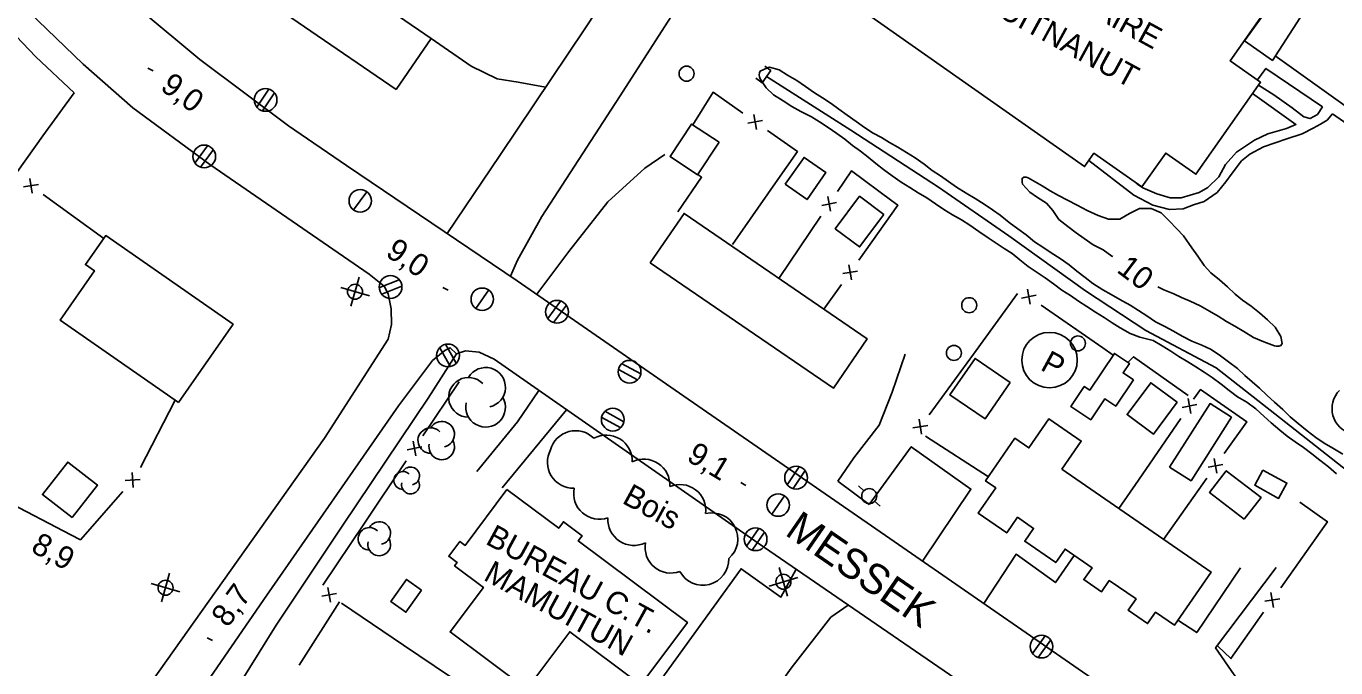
# Model space of a CAD drawing. Extents: x 219136 to 222520, y 5421589 to 5424530.
# Drawn here: x 221189.4 to 221364.2, y 5423246.8 to 5423332.5 of the extents above; entities that cross this region are included whole.
import ezdxf

# ---------------------------------------------------------------- set-up
doc = ezdxf.new("R2010")
doc.units = 0
for name, color, linetype in [('Level 1', 7, 'Continuous'), ('Level 19', 7, 'Continuous'), ('Level 2', 7, 'Continuous'), ('Level 21', 7, 'Continuous'), ('Level 22', 7, 'Continuous'), ('Level 26', 7, 'Continuous'), ('Level 3', 7, 'Continuous'), ('Level 31', 7, 'Continuous'), ('Level 36', 7, 'Continuous'), ('Level 37', 7, 'Continuous'), ('Level 38', 7, 'Continuous'), ('Level 4', 7, 'Continuous'), ('Level 44', 7, 'Continuous'), ('Level 52', 7, 'Continuous')]:
    doc.layers.add(name, color=color, linetype=linetype)

msp = doc.modelspace()

# ---------------------------------------------------------------- linework, layer by layer
at = {"layer": 'Level 1'}
for points in [[(221334.39, 5423301.7), (221334.28, 5423301.77), (221333.12, 5423302.6), (221331.78, 5423303.29), (221330.57, 5423304.11), (221329.51, 5423304.88), (221328.39, 5423305.71), (221327.21, 5423306.67), (221326.39, 5423307.87), (221325.54, 5423308.83), (221324.37, 5423309.6), (221323.34, 5423310.31), (221322.37, 5423311.37), (221322.31, 5423311.62), (221322.3, 5423312.14), (221322.54, 5423312.31), (221322.83, 5423312.29), (221323.11, 5423312.21), (221324.96, 5423311.14), (221326.03, 5423310.48), (221327.16, 5423309.85), (221328.35, 5423309.24), (221329.64, 5423308.56), (221330.99, 5423307.85), (221332.43, 5423307.21), (221333.85, 5423306.68), (221335.36, 5423306.71), (221336.64, 5423307.46)], [(221336.64, 5423307.46), (221337.98, 5423308.12), (221339.54, 5423308.11), (221340.84, 5423307.53), (221341.92, 5423306.49), (221342.96, 5423305.43), (221343.85, 5423304.46), (221344.97, 5423302.88), (221345.73, 5423301.75), (221346.58, 5423300.53), (221347.5, 5423299.54), (221348.65, 5423298.59), (221349.69, 5423297.65), (221350.72, 5423296.7), (221351.7, 5423295.89), (221352.87, 5423295.09), (221353.99, 5423294.18), (221355.03, 5423293.26), (221356.08, 5423292.28), (221356.84, 5423291.06), (221357, 5423290.1), (221356.84, 5423289.85), (221356.56, 5423289.75), (221356.24, 5423289.75), (221355.96, 5423289.8), (221354.54, 5423290.31), (221353.18, 5423290.93), (221351.87, 5423291.71), (221350.67, 5423292.41), (221349.59, 5423293.05), (221348.48, 5423293.75), (221347.32, 5423294.43), (221346.08, 5423295.15), (221344.72, 5423295.75), (221343.57, 5423296.23), (221342.53, 5423296.74)], [(221342.53, 5423296.74), (221341.2, 5423297.25), (221340.4, 5423297.67)]]:
    msp.add_lwpolyline(points, dxfattribs=at)
at = {"layer": 'Level 19'}
for points in [[(221243.46, 5423330.83), (221248.79, 5423327.14), (221252.25, 5423325.43), (221255.05, 5423325), (221258.72, 5423324.32), (221258.72, 5423324.32)], [(221188.24, 5423313.07), (221191.65, 5423317.82), (221195.82, 5423323.56)], [(221257.56, 5423296.68), (221261.82, 5423302.4), (221267.04, 5423309), (221271.97, 5423313.5), (221274.63, 5423315.35)], [(221297.7, 5423271.73), (221299.84, 5423274.83), (221303.25, 5423279.2), (221304.96, 5423283.62), (221306.72, 5423288.7)], [(221249.54, 5423273.01), (221254.97, 5423279.64), (221257.8, 5423283.85)], [(221261.53, 5423281.26), (221252.91, 5423270.85)], [(221301.91, 5423268.64), (221307.52, 5423276.33), (221315.47, 5423270.68), (221308.99, 5423261.08)], [(221317.2, 5423255.4), (221321.49, 5423261.98), (221326.75, 5423258.19), (221329.25, 5423261.83)], [(221351.46, 5423260.17), (221345.61, 5423251.52), (221343.1, 5423253.2)], [(221356.18, 5423260.23), (221348.12, 5423249.48), (221350.59, 5423245.9), (221354.2, 5423241.31), (221357.6, 5423238.87), (221360.7, 5423236.89), (221366.13, 5423232.73), (221367.98, 5423235.4)]]:
    msp.add_lwpolyline(points, dxfattribs=at)
at = {"layer": 'Level 2'}
for points in [[(221302.45, 5423318.2), (221301.29, 5423318.95), (221300.14, 5423319.75), (221298.96, 5423320.58), (221297.85, 5423321.39), (221296.81, 5423322.13), (221295.66, 5423322.88), (221294.6, 5423323.54), (221293.38, 5423324.42), (221292.23, 5423325.22), (221291.02, 5423325.94), (221289.89, 5423326.65), (221288.6, 5423326.98), (221288.32, 5423326.92), (221287.36, 5423326.47), (221287.26, 5423326.22), (221287.23, 5423325.96), (221287.26, 5423325.69), (221287.34, 5423325.44), (221288.13, 5423324.23), (221289.14, 5423323.28), (221290.44, 5423322.48), (221291.59, 5423321.76), (221292.79, 5423321.09), (221294.19, 5423320.38), (221295.27, 5423319.71), (221296.42, 5423318.95), (221297.57, 5423318.14), (221298.64, 5423317.36), (221299.68, 5423316.55), (221300.73, 5423315.77), (221301.76, 5423314.97), (221302.78, 5423314.13), (221303.8, 5423313.31), (221304.95, 5423312.47), (221306.18, 5423311.63), (221307.3, 5423310.91), (221308.45, 5423310.22), (221309.61, 5423309.53), (221310.76, 5423308.74), (221311.88, 5423307.98), (221313.03, 5423307.3), (221314.22, 5423306.61), (221315.32, 5423305.92), (221316.55, 5423305.06), (221317.77, 5423304.2), (221318.84, 5423303.5), (221319.93, 5423302.78), (221320.99, 5423302.1), (221321.98, 5423301.26), (221323.1, 5423300.4), (221324.31, 5423299.57), (221325.38, 5423298.85), (221326.48, 5423298.09), (221327.6, 5423297.24), (221328.75, 5423296.5), (221329.83, 5423295.78), (221330.94, 5423295.03), (221332.1, 5423294.31), (221333.23, 5423293.59), (221334.31, 5423292.88), (221335.38, 5423292.18), (221336.71, 5423291.46), (221338.02, 5423290.94), (221338.54, 5423290.83)], [(221365.11, 5423275.36), (221363.76, 5423276.13), (221362.6, 5423276.79), (221361.5, 5423277.56), (221360.35, 5423278.47), (221359.13, 5423279.45), (221358.09, 5423280.34), (221357.08, 5423281.28), (221356, 5423282.28), (221354.94, 5423283.21), (221353.96, 5423284.13), (221352.99, 5423284.98), (221352, 5423285.84), (221351.04, 5423286.78), (221349.82, 5423287.64), (221348.61, 5423288.59), (221347.46, 5423289.34), (221346.29, 5423289.87), (221344.97, 5423290.42), (221343.64, 5423291.1), (221342.52, 5423291.75), (221341.34, 5423292.39), (221340.11, 5423293.01), (221338.94, 5423293.79), (221337.82, 5423294.52), (221336.7, 5423295.24), (221335.35, 5423295.99), (221334.18, 5423296.65), (221333.07, 5423297.28), (221331.75, 5423298.12), (221330.7, 5423298.92), (221329.61, 5423299.77), (221328.56, 5423300.6), (221327.36, 5423301.43), (221326.2, 5423302.19), (221325.06, 5423302.95), (221323.97, 5423303.69), (221322.86, 5423304.59), (221321.71, 5423305.42), (221320.57, 5423306.26), (221319.39, 5423307.23), (221318.37, 5423307.96), (221317.24, 5423308.7), (221316.06, 5423309.47), (221314.82, 5423310.18), (221313.54, 5423310.97), (221312.49, 5423311.72), (221311.4, 5423312.47), (221310.32, 5423313.2), (221309.24, 5423314.03), (221308.04, 5423314.88), (221306.88, 5423315.6), (221305.74, 5423316.29), (221304.63, 5423316.94), (221303.56, 5423317.59), (221302.45, 5423318.2)], [(221338.54, 5423290.83), (221339.79, 5423290.49), (221340.99, 5423289.81), (221342.14, 5423289.09), (221343.21, 5423288.38), (221344.4, 5423287.65), (221345.5, 5423286.98), (221346.58, 5423286.29), (221347.68, 5423285.56), (221348.85, 5423284.7), (221349.93, 5423283.83), (221351.06, 5423283.01), (221352.3, 5423282.28), (221353.49, 5423281.38), (221354.59, 5423280.35), (221355.54, 5423279.51), (221356.71, 5423278.53), (221357.69, 5423277.74), (221358.72, 5423276.99), (221359.83, 5423276.22), (221360.95, 5423275.38), (221362.03, 5423274.55), (221363.17, 5423273.64), (221364.25, 5423272.71)]]:
    msp.add_lwpolyline(points, dxfattribs=at)
at = {"layer": 'Level 21'}
for points in [[(221166.57, 5423470.95), (221167.05, 5423466.85), (221167.99, 5423465.31), (221169.33, 5423463.67), (221170.84, 5423462.49), (221172.03, 5423461.9), (221173.9, 5423444.53), (221176.37, 5423413.28), (221177.95, 5423395.01), (221178.79, 5423388.11), (221180.59, 5423381.09), (221181.46, 5423378.86), (221186.24, 5423366.21), (221184.71, 5423363.79), (221184.17, 5423361.06), (221184.79, 5423358.59), (221185.99, 5423356.51), (221188.89, 5423351.93), (221194.15, 5423345.11), (221198.89, 5423340.19), (221204.64, 5423334.62), (221212.6, 5423328.01), (221224.42, 5423319.14), (221232.14, 5423313.85)], [(221245.61, 5423304.77), (221252.61, 5423315.21), (221264.03, 5423332.23), (221275.63, 5423349.82), (221288.07, 5423368.7), (221299.26, 5423385.38), (221309.36, 5423398.65), (221319.83, 5423409.55), (221328.62, 5423417.49)], [(221335.26, 5423410.11), (221329.06, 5423403.64), (221327.51, 5423400.23), (221322.49, 5423394.42), (221319.72, 5423395.45), (221317.02, 5423394.19), (221314.06, 5423390.87), (221310.44, 5423385.78), (221301.43, 5423371.69), (221293.71, 5423361.29), (221281.55, 5423343.25), (221268.57, 5423323.02), (221258.2, 5423307.05), (221254.98, 5423301.25), (221254.03, 5423299.11)], [(221195.82, 5423323.56), (221190.7, 5423328.36), (221187.21, 5423332.07), (221180.66, 5423340.32), (221175.98, 5423347.03), (221172.93, 5423353.25), (221170.5, 5423359.06), (221169.55, 5423362.68)], [(221187.7, 5423218.3), (221205.22, 5423243.64), (221229.21, 5423277.47), (221237.71, 5423290.69), (221238.14, 5423292.63), (221238.13, 5423294.72), (221237.7, 5423296.72), (221237.17, 5423297.75), (221235.16, 5423299.35), (221213.94, 5423313.98), (221203.63, 5423321.56), (221197.02, 5423327.41), (221187.38, 5423336.74)], [(221232.14, 5423313.85), (221254.94, 5423298.49), (221276.61, 5423283.49), (221305.25, 5423263.67), (221335.68, 5423242.61), (221372.49, 5423217.23)], [(221160.77, 5423162.07), (221179.61, 5423192.27), (221195.24, 5423218.18), (221207.37, 5423235.95), (221221.52, 5423256.52), (221239.08, 5423281.8), (221243.65, 5423287.85), (221245.26, 5423289.18), (221245.97, 5423289.53), (221246.85, 5423288.72), (221248.05, 5423289.14), (221249.86, 5423288.94), (221251.84, 5423288), (221287.09, 5423263.46), (221326.07, 5423236.66), (221356.72, 5423215.77), (221381.01, 5423198.93), (221382.03, 5423197.83), (221382.77, 5423196), (221383.04, 5423193.74), (221382.84, 5423191.9), (221382.48, 5423188.97), (221374.16, 5423163.4), (221366.95, 5423136.57)], [(221246.85, 5423288.72), (221243.05, 5423282.81), (221231.66, 5423265.88), (221222.75, 5423252.5), (221214.52, 5423239.23), (221207.59, 5423226.74), (221198.22, 5423212.24), (221189.81, 5423198.56), (221182.61, 5423188.58), (221175.53, 5423179.21), (221170.03, 5423170.75), (221165.83, 5423165.23), (221163.7, 5423164.25), (221162.66, 5423162.72), (221162.1, 5423161.37)], [(221301.91, 5423268.64), (221297.7, 5423271.73)]]:
    msp.add_lwpolyline(points, dxfattribs=at)
at = {"layer": 'Level 22'}
for points in [[(221356.08, 5423328.5), (221375.51, 5423314.62)], [(221362.37, 5423321.69), (221354.84, 5423326.81), (221353.7, 5423325.28)], [(221353.06, 5423323.46), (221358.84, 5423319.35), (221357.57, 5423318.81), (221355.07, 5423318.07), (221353.32, 5423317.24), (221350.89, 5423315.65), (221349.44, 5423314), (221348.56, 5423312.35), (221347.1, 5423310.92), (221345.91, 5423310.27), (221343.54, 5423309.55), (221342.04, 5423309.57), (221340.26, 5423310.1), (221338.39, 5423310.88), (221337.62, 5423311.41)], [(221362.37, 5423321.69), (221361.7, 5423320.68), (221360.76, 5423320.13), (221359.9, 5423320.38), (221358.34, 5423321.58), (221355.9, 5423323.3), (221353.84, 5423324.58)], [(221331.19, 5423314.51), (221337.21, 5423309.9), (221339.73, 5423308.58), (221341.96, 5423308.01), (221343.78, 5423308.1), (221345.16, 5423308.6), (221346.58, 5423309.06), (221348.31, 5423310.28), (221349.5, 5423311.69), (221350.33, 5423312.85), (221351.56, 5423314.48), (221352.69, 5423315.38), (221354.53, 5423316.35), (221357.61, 5423317.44), (221359.68, 5423318.09), (221361.13, 5423318.86), (221362.1, 5423319.38), (221363, 5423319.91), (221363.72, 5423320.76)], [(221372.85, 5423314.4), (221363.72, 5423320.76)]]:
    msp.add_lwpolyline(points, dxfattribs=at)
at = {"layer": 'Level 26'}
for p, q in [((221288.79, 5423326.54), (221287.98, 5423327.13)), ((221287.6, 5423324.91), (221286.79, 5423325.5)), ((221288.79, 5423326.54), (221287.6, 5423324.91))]:
    msp.add_line(p, q, dxfattribs=at)
at = {"layer": 'Level 3'}
for p, q in [((221205.65, 5423326.86), (221206.35, 5423326.48)), ((221245.01, 5423297.59), (221245.71, 5423297.21)), ((221284.76, 5423271.54), (221285.46, 5423271.16)), ((221213.56, 5423250.83), (221214.27, 5423250.45))]:
    msp.add_line(p, q, dxfattribs=at)
at = {"layer": 'Level 31'}
for points in [[(221238.79, 5423324.01), (221214.32, 5423340.76), (221218.99, 5423347.58), (221243.46, 5423330.83)], [(221281.87, 5423316.96), (221279.01, 5423312.63), (221275.34, 5423315.06), (221278.19, 5423319.39)], [(221290.7, 5423311.36), (221293.21, 5423314.95), (221296.12, 5423312.91), (221293.61, 5423309.32)], [(221303.87, 5423307.31), (221300.61, 5423302.99), (221297.36, 5423305.43), (221300.62, 5423309.76)], [(221272.68, 5423300.88), (221297.12, 5423284.13), (221301.63, 5423290.71), (221277.19, 5423307.46)], [(221209.73, 5423282.22), (221193.93, 5423293.23), (221198.52, 5423299.81), (221197.33, 5423300.64), (221200.04, 5423304.51), (221217.02, 5423292.68)], [(221337.15, 5423285.26), (221334.79, 5423281.76), (221333.35, 5423282.73), (221331.46, 5423279.93), (221328.8, 5423281.72), (221330.6, 5423284.39), (221331.33, 5423283.9), (221334.62, 5423288.79), (221336.63, 5423287.44), (221335.78, 5423286.18)], [(221320.7, 5423284.92), (221317.36, 5423280.04), (221312.68, 5423283.24), (221316.03, 5423288.12)], [(221342.98, 5423282.27), (221339.84, 5423278.02), (221336.32, 5423280.62), (221339.47, 5423284.87)], [(221341.99, 5423273.62), (221347.38, 5423282.08), (221350.24, 5423280.26), (221344.85, 5423271.8)], [(221327.61, 5423273.33), (221347.52, 5423259.6), (221342.62, 5423252.51), (221340.09, 5423254.25), (221339.04, 5423252.73), (221336.46, 5423254.51), (221337.5, 5423256.02), (221333.94, 5423258.47), (221332.89, 5423256.95), (221330.52, 5423258.59), (221331.63, 5423260.19), (221328.03, 5423262.67), (221326.79, 5423260.87), (221322.65, 5423263.72), (221323.84, 5423265.43), (221321.7, 5423266.91), (221320.25, 5423264.82), (221316.45, 5423267.45), (221318.78, 5423270.83), (221317.42, 5423271.77), (221321.34, 5423277.46), (221323.2, 5423276.18), (221325.88, 5423280.06), (221330.19, 5423277.09)], [(221195.56, 5423266.87), (221198.93, 5423271.22), (221194.96, 5423274.29), (221191.59, 5423269.94)], [(221351.94, 5423266.65), (221347.3, 5423270.23), (221349.54, 5423273.13), (221354.18, 5423269.55)], [(221354.44, 5423273.21), (221357.63, 5423271.47), (221356.52, 5423269.44), (221353.34, 5423271.18)], [(221253.57, 5423270.61), (221260.47, 5423265.46), (221261.11, 5423266.32), (221263.6, 5423264.46), (221263.08, 5423263.77), (221277.64, 5423252.89), (221271.42, 5423244.56), (221261.94, 5423251.64), (221256.22, 5423243.97), (221245.98, 5423251.61), (221250.42, 5423257.56), (221246.57, 5423260.44), (221246.9, 5423260.89), (221245.8, 5423261.71), (221247.28, 5423263.69), (221248, 5423263.15)], [(221242.18, 5423257.17), (221240.09, 5423254.23), (221238.06, 5423255.68), (221240.15, 5423258.62)]]:
    msp.add_lwpolyline(points, close=True, dxfattribs=at)
msp.add_lwpolyline([(221354.39, 5423333.98), (221350.07, 5423327.82), (221354.12, 5423324.98), (221345.49, 5423312.69), (221341.46, 5423315.52), (221338.29, 5423311.01), (221331.88, 5423315.5), (221330.64, 5423313.73), (221301.34, 5423334.29)], dxfattribs=at)
at = {"layer": 'Level 36'}
for p, q in [((221221.79, 5423324.07), (221220.18, 5423321.66)), ((221220.95, 5423321.17), (221222.56, 5423323.58)), ((221213.63, 5423316.51), (221211.93, 5423314.16)), ((221212.69, 5423313.63), (221214.39, 5423315.98)), ((221234.88, 5423310.36), (221233.1, 5423307.94)), ((221233.84, 5423298.94), (221232.74, 5423295.11)), ((221231.38, 5423297.58), (221235.21, 5423296.48)), ((221239.18, 5423298.62), (221236.49, 5423297.52)), ((221236.86, 5423296.68), (221239.55, 5423297.78)), ((221251.13, 5423297.25), (221249.41, 5423294.79)), ((221260.73, 5423295.77), (221259.01, 5423293.44)), ((221259.77, 5423292.91), (221261.49, 5423295.24)), ((221246.81, 5423287.48), (221245.38, 5423290)), ((221244.59, 5423289.52), (221246.02, 5423287)), ((221268.45, 5423286.64), (221270.99, 5423285.25)), ((221271.41, 5423286.06), (221268.87, 5423287.45)), ((221266.21, 5423280.25), (221268.75, 5423278.86)), ((221269.17, 5423279.67), (221266.63, 5423281.06)), ((221292.57, 5423273.66), (221290.97, 5423271.23)), ((221291.75, 5423270.74), (221293.35, 5423273.17)), ((221300.45, 5423271.12), (221301.17, 5423270.43)), ((221288.9, 5423267.31), (221290.6, 5423269.77)), ((221303.36, 5423268.38), (221302.62, 5423269.05)), ((221287.17, 5423265.42), (221285.52, 5423263.04)), ((221286.29, 5423262.54), (221287.94, 5423264.92)), ((221208.56, 5423259.44), (221207.46, 5423255.61)), ((221288.54, 5423257.74), (221292.37, 5423258.87)), ((221291.02, 5423256.39), (221289.89, 5423260.22)), ((221206.1, 5423258.08), (221209.93, 5423256.98)), ((221325.37, 5423251.1), (221323.67, 5423248.75)), ((221324.43, 5423248.22), (221326.13, 5423250.57))]:
    msp.add_line(p, q, dxfattribs=at)
for centre, radius in [((221277.53, 5423326.12), 1), ((221221.36, 5423322.62), 1.52), ((221213.17, 5423315.07), 1.52), ((221233.99, 5423309.14), 1.5), ((221238.03, 5423297.65), 1.52), ((221233.29, 5423297.02), 1), ((221250.27, 5423296.01), 1.5), ((221260.24, 5423294.34), 1.52), ((221315.24, 5423295.22), 1), ((221245.7, 5423288.51), 1.52), ((221329.75, 5423290.12), 1), ((221313.2, 5423288.85), 1), ((221269.93, 5423286.34), 1.52), ((221267.69, 5423279.95), 1.52), ((221292.15, 5423272.2), 1.52), ((221301.9, 5423269.74), 1), ((221289.75, 5423268.55), 1.5), ((221286.74, 5423263.98), 1.52), ((221208.01, 5423257.52), 1), ((221290.46, 5423258.31), 1), ((221324.89, 5423249.66), 1.52)]:
    msp.add_circle(centre, radius, dxfattribs=at)
at = {"layer": 'Level 37'}
for p, q in [((221285.71, 5423319.51), (221287.68, 5423319.85)), ((221286.87, 5423318.69), (221286.52, 5423320.67)), ((221191.05, 5423311.32), (221189.07, 5423311.01)), ((221189.9, 5423312.15), (221190.21, 5423310.17)), ((221296.75, 5423307.75), (221296.37, 5423309.72)), ((221297.54, 5423308.93), (221295.58, 5423308.54)), ((221299.19, 5423300.59), (221299.53, 5423298.62)), ((221298.37, 5423299.44), (221300.35, 5423299.77)), ((221323.38, 5423295.37), (221323.03, 5423297.34)), ((221322.22, 5423296.18), (221324.19, 5423296.54)), ((221343.65, 5423281.58), (221345.61, 5423281.95)), ((221344.45, 5423282.75), (221344.81, 5423280.78)), ((221308.89, 5423278.01), (221308.57, 5423279.99)), ((221309.72, 5423279.15), (221307.74, 5423278.84)), ((221242.21, 5423276.3), (221240.25, 5423275.92)), ((221241.42, 5423275.13), (221241.04, 5423277.09)), ((221348.28, 5423272.79), (221347.94, 5423274.76)), ((221203.68, 5423270.88), (221203.55, 5423272.87)), ((221349.1, 5423273.94), (221347.13, 5423273.6)), ((221204.61, 5423271.94), (221202.62, 5423271.81)), ((221230.82, 5423256.75), (221228.86, 5423256.37)), ((221229.65, 5423257.54), (221230.03, 5423255.58)), ((221355.85, 5423254.88), (221355.51, 5423256.86)), ((221356.67, 5423256.04), (221354.69, 5423255.7))]:
    msp.add_line(p, q, dxfattribs=at)
for points in [[(221278.37, 5423319.27), (221281.07, 5423323.63), (221285.06, 5423320.83)], [(221288.33, 5423318.53), (221292.33, 5423315.72), (221289.41, 5423311.53)], [(221276.37, 5423307.66), (221279.53, 5423312.29), (221279.03, 5423312.67)], [(221297.68, 5423310.39), (221299.52, 5423313.13), (221304.92, 5423309.16)], [(221289.41, 5423311.53), (221283.68, 5423303.33)], [(221199.76, 5423304.1), (221191.68, 5423309.99)], [(221304.92, 5423309.16), (221305.73, 5423308.56), (221300.52, 5423301.23)], [(221289.86, 5423298.78), (221295.44, 5423307.08)], [(221298.2, 5423297.97), (221295.85, 5423294.67)], [(221315.8, 5423288.7), (221321.68, 5423296.78)], [(221324.85, 5423295.22), (221333.07, 5423289.52)], [(221309.91, 5423280.61), (221315.8, 5423288.7)], [(221333.07, 5423289.52), (221334.46, 5423288.56)], [(221336.42, 5423287.58), (221337.17, 5423288.34), (221344.46, 5423283.18)], [(221242.34, 5423277.77), (221247.19, 5423285)], [(221348.34, 5423282.4), (221346.09, 5423283.96), (221345.18, 5423282.67)], [(221204.69, 5423273.54), (221209.23, 5423282.46)], [(221209.23, 5423282.46), (221209.27, 5423282.54)], [(221349.27, 5423275.41), (221352.27, 5423279.66), (221348.34, 5423282.4)], [(221343.5, 5423280.12), (221337.84, 5423271.87)], [(221317.8, 5423272.31), (221309.39, 5423277.72)], [(221234.55, 5423266.14), (221240.12, 5423274.45)], [(221337.84, 5423271.87), (221335.23, 5423268.08)], [(221341.19, 5423263.97), (221346.96, 5423272.14)], [(221186.51, 5423269.18), (221195.39, 5423264.58)], [(221195.39, 5423264.58), (221196.66, 5423263.92), (221202.3, 5423270.37)], [(221362.59, 5423265.68), (221363.04, 5423266.31), (221359.35, 5423268.93)], [(221228.98, 5423257.84), (221234.55, 5423266.14)], [(221356.83, 5423257.5), (221362.59, 5423265.68)], [(221231.23, 5423255.62), (221225.86, 5423247.18)], [(221239.78, 5423249.84), (221231.5, 5423255.44)], [(221348.41, 5423249.73), (221350.17, 5423248.05), (221354.53, 5423254.24)], [(221248.07, 5423244.24), (221239.78, 5423249.84)]]:
    msp.add_lwpolyline(points, dxfattribs=at)
at = {"layer": 'Level 38'}
msp.add_circle((221325.96, 5423287.89), 3.7, dxfattribs=at)
at = {"layer": 'Level 4'}
msp.add_lwpolyline([(221288.2, 5423325.73), (221299.46, 5423318.57), (221311.16, 5423310.98), (221320.51, 5423304.48), (221330.75, 5423297.15), (221338.79, 5423291.85), (221348.18, 5423286.88), (221356.02, 5423280.71), (221365.03, 5423273.67), (221372.84, 5423267.78), (221380.52, 5423261.23), (221388.07, 5423254.55), (221395.84, 5423249.95), (221403.51, 5423245.81)], dxfattribs=at)
at = {"layer": 'Level 44'}
for centre, radius, start, end in [((221250.72, 5423284.25), 2.65, 282.2692, 149.7262), ((221248.44, 5423282.92), 2.65, 44.1153, 269.8039), ((221367.12, 5423281.42), 3.46, 135.3788, 255.3788), ((221250.72, 5423281.6), 2.65, 166.9368, 29.6212), ((221244.86, 5423278), 1.7, 282.2692, 149.7262), ((221243.39, 5423277.15), 1.7, 44.1153, 269.8039), ((221262.72, 5423275.01), 3.46, 45.0941, 165.0941), ((221266.82, 5423274.42), 3.46, 358.443, 118.443), ((221244.86, 5423276.3), 1.7, 166.9368, 29.6212), ((221262.42, 5423274.26), 3.46, 151.6534, 271.6534), ((221271.83, 5423271.22), 3.46, 356.5395, 116.5395), ((221239.67, 5423271.83), 1.19, 44.1153, 269.8039), ((221240.7, 5423272.43), 1.19, 282.2692, 149.7262), ((221240.7, 5423271.23), 1.19, 166.9368, 29.6212), ((221265.92, 5423270.11), 3.46, 168.6919, 288.6919), ((221276.64, 5423267.83), 3.46, 352.9719, 112.9719), ((221280.91, 5423264.04), 3.46, 310.6725, 103.8587), ((221235.23, 5423264.04), 1.51, 44.1153, 269.8039), ((221236.52, 5423264.8), 1.51, 282.2692, 149.7262), ((221270.49, 5423266.62), 3.46, 176.5313, 296.5313), ((221236.52, 5423263.29), 1.51, 166.9368, 29.6212), ((221275.45, 5423262.93), 3.46, 170.1576, 290.1576), ((221279.7, 5423261.31), 3.46, 208.0011, 1.7373)]:
    msp.add_arc(centre, radius, start, end, dxfattribs=at)
at = {"layer": 'Level 52'}
for points in [[(221303.92, 5423375.59), (221305.86, 5423376.52), (221308.57, 5423377.52), (221311.19, 5423377.77), (221313.39, 5423377.24), (221315.48, 5423375.95), (221319.17, 5423373.45), (221316.36, 5423369.11), (221350.45, 5423343.71), (221354.62, 5423349.45), (221360.28, 5423345.36), (221360.62, 5423344.81), (221361, 5423343.74), (221360.73, 5423342.65), (221360.43, 5423342.21), (221351.98, 5423330.49), (221355.69, 5423327.89), (221363.51, 5423339.97), (221364.59, 5423340.97)], [(221299.1, 5423255.2), (221296.8, 5423253.59), (221291.51, 5423246.79), (221283.78, 5423236), (221288.18, 5423232.4), (221281.4, 5423223.01), (221270.66, 5423230.09), (221274.51, 5423235.25), (221269.48, 5423238.82), (221284.8, 5423260.04), (221290.11, 5423256.26), (221292.15, 5423259.98)]]:
    msp.add_lwpolyline(points, dxfattribs=at)

# ---------------------------------------------------------------- texts
at = {"layer": 'Level 1'}
msp.add_text('10', height=3, rotation=323.0756, dxfattribs=at).set_placement((221334.79, 5423299.73))
at = {"layer": 'Level 21'}
msp.add_text('MESSEK', height=4, rotation=325.4902, dxfattribs=at).set_placement((221290.51, 5423264.65))
at = {"layer": 'Level 3'}
for s, rotation, p in [('9,0', 323.7969, (221207.17, 5423324.05)), ('9,0', 326.1761, (221237.22, 5423301.88)), ('9,1', 328.79, (221277.38, 5423274.57)), ('8,9', 331.383, (221189.89, 5423262.4)), ('8,7', 53.6209, (221216.31, 5423252.08))]:
    msp.add_text(s, height=3, rotation=rotation, dxfattribs=at).set_placement(p)
at = {"layer": 'Level 31'}
for s, p in [('COMMUNAUTAIRE', (221308.37, 5423346.5)), ('KAMAMUITNANUT', (221306.07, 5423340.89)), ('BUREAU C.T.', (221250.56, 5423263.44)), ('MAMUITUN', (221250.29, 5423258.63))]:
    msp.add_text(s, height=3, rotation=331.3547, dxfattribs=at).set_placement(p)
at = {"layer": 'Level 38'}
msp.add_text('P', height=3, rotation=331.383, dxfattribs=at).set_placement((221324.6, 5423286.67))
at = {"layer": 'Level 44'}
msp.add_text('Bois', height=3, rotation=331.3547, dxfattribs=at).set_placement((221268.79, 5423268.88))

doc.saveas('drawing.dxf')
